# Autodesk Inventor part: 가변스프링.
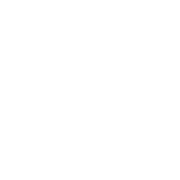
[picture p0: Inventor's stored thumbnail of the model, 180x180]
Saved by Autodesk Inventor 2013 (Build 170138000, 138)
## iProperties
Created: 2018-10
Part Number: 가변스프링.
Material: 일반
Document SubType Name: Modeling
Designer: Administrator
Density: 1 g/cm^3
Mass: 0.778196 g
Surface Area: 15.7864 cm^2
Volume: 0.778196 cm^3
Author: Administrator
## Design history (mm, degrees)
sketch "스케치1"
  geometry: L1 (0, 0)-(0, 29.23); L2 (0, 0)-(8, 0); L3 (0, 29.23)-(8, 29.23); C1 r 1 at (8, 0)
  constraints: 6 end point, 1 centre point, 1 coincident, 1 parallel, 1 perpendicular, 1 vertical
  dimensions: "d0" = 29.23004 distance of L1.start L1.end (derived); "d1" = 8 distance of L1.start L2.end; "d2" = 2 diameter of C1; "d3" = 8 distance of L1.end L3.end
feature "코일1" sketch "스케치1" pitch "d4" = 10; turns "d6" = 5; dims "d5" = 29.23004 (= d0), "d7" = 0, angle "d8" = 90 deg, angle "d9" = 90 deg, "d10" = 0, "d11" = 0
sketch "스케치2"
  geometry: L1 (29.23, 11)-(0, 11); L2 (0, 11)-(0, -11); L3 (0, -11)-(29.23, -11); L4 (29.23, -11)-(29.23, 11); 2 further points
  constraints: 8 end point, 2 parallel, 1 coincident, 1 horizontal, 1 midpoint, 1 perpendicular
  dimensions: "d12" = 29.23004 distance of L1.start L1.end (derived); "d14" = 22 distance of L3.end L1.start
extrude "돌출1" sketch "스케치2" stored distance "d15" = 0; taper "d16" = 0 deg
node "솔리드1"
